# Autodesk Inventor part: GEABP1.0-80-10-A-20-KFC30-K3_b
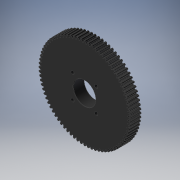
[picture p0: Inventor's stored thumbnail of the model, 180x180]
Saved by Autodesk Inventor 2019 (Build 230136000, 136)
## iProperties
Created: 2022-11
Part Number: GEABP1.0-80-10-A-20-KFC30-K3_b
Material: Generic
Catalog Web Link: www.cadenas.de
Description: GEABM, GEABMS, GEABMT, GEABP, GEABPS, GEABPT, GEABA, GEABAS, GEABAT_body-Plastic Spur Gears - Pressure Angle 20 Degrees, Module 0.5/0.8/1.0/1.5/2.0/2.5/3.0
Vendor: MISUMI
Document SubType Name: Modeling
Designer: psAdmin
Manufacturer: MISUMI
Mass: 46.6006 g
Surface Area: 152.098 cm^2
Volume: 46.6006 cm^3
Density: 1 g/cm^3
Appearance: PSOLRGB-175-175-175
Category: PARTsolutions
Company: MISUMI
Title: GEABP1.0-80-10-A-20-KFC30-K3
Author: Cadenas PARTsolutions
Comments: Plastic Spur Gears - Pressure Angle 20 Degrees, Module 0.5/0.8/1.0/1.5/2.0/2.5/3.0
PSOL_IDENT_0: {$CADENAS_DATA/23d-libs/misumi/metric/54_spur_gears/geabms20/geabms20.prj},408 {VTYP=3D},{NB=GEABP1.
PSOL_IDENT_1: 0-80-10-A-20-KFC30-K3_b},{LINA=GEABP1.0-80-10-A-20-KFC30-K3},{NN=GEABM, GEABMS, GEABMT, GEABP, GEABP
PSOL_IDENT_2: S, GEABPT, GEABA, GEABAS, GEABAT_body},{DATE=17.10.2022 23:48:33},{GEOMDATE=14.09.2022 05:11:00},{VE
PSOL_IDENT_3: RSION=},{LINEID=30},{WBVAR=MATSG,MATCR,NT,B,TS,PS,ALT1,ALT2,TPC,ALT11,ALT10,BS,ALT3,Z,J,ALT4,Q,R,S,T
PSOL_IDENT_4: ,ALT5,LFC,LTC,MALT5,ALT6,KFC,KTC,K},{WBNUMERIC=NT,B,BS,Z,J,Q,R,S,T,LFC,LTC,KFC,KTC,K}  {NB=GEABP1.0-
PSOL_IDENT_5: 80-10-A-20-KFC30-K3_b},{LINA=GEABP1.0-80-10-A-20-KFC30-K3},{KT=DUMMY},{PN=GEABP1.0-80-10-A-20-KFC30-
PSOL_IDENT_6: K3},{TYPE=GEABP},{MATSG=PW},{MATSGALG='MCN','MC Nylon','PW','Polyacetal White','PB','Polyacetal Blue'
PSOL_IDENT_7: },{MATCR=},{MATCRALG='','-','S45C','1045 Carbon Steel','SUS304','304 Stainless Steel'},{MOD=1.0},{MO
PSOL_IDENT_8: D1=1.0},{NT=80},{NTALG=15,16,18,20,22,24,25,26,28,30,32,35,36,40,45,48,50,55,60,70,75,80,90,100,120}
PSOL_IDENT_9: ,{B=10},{BALG=10,15},{TS=A},{TSALG='A','A','B','B'},{TSPN=-A},{PS=20},{PSALG='10','10','11','11','12'
PSOL_IDENT_10: ,'12','13','13','14','14','15','15','16','16','17','17','18','18','19','19','20','20','21','21','22'
PSOL_IDENT_11: ,'22','23','23','24','24','25','25','26','26','27','27','28','28'},{PSCRL='10','10','11','11','12','
PSOL_IDENT_12: 12','13','13','14','14','15','15','16','16','17','17','18','18','19','19','20','20','21','21','22','
PSOL_IDENT_13: 22','23','23','24','24','25','25','26','26','27','27','28','28'},{PSCRW='10','10','12','12','15','15'
PSOL_IDENT_14: ,'20','20'},{DD=80.0},{DD05=40},{DD08=64},{DD10=80},{DD15=120},{DD20=0},{DD25=0},{DD30=0},{D=82.0},{
PSOL_IDENT_15: D05=41},{D08=65.6},{D10=82},{D15=123},{D20=0},{D25=0},{D30=0},{G=77.50},{G05=38.75},{G08=62},{G10=77
PSOL_IDENT_16: .5},{G15=116.25},{G20=0},{G25=0},{G30=0},{H=0.0},{L=0},{LL1=0},{LL2=0.0},{M=-},{M3D=0},{P=20.00},{DD
PSOL_IDENT_17: 1=0},{CIFR=15},{CIFM=0},{CIFK=0},{CIFTAP=0},{ALT1=},{ALT1ALG='','Not applicable'},{ALT1PN=},{ALT2=},
PSOL_IDENT_18: {ALT2ALG='','Not applicable'},{TPC=N/A},{TPCALG='N/A'},{ALT2PN=},{KC=0},{ALT11=},{ALT11ALG='','Not a
PSOL_IDENT_19: pplicable'},{ALT11PN=},{DEG=0},{ALT10=},{ALT10ALG= '','Not applicable' },{ALT10PN=},{BS=0.0},{BSALG=
PSOL_IDENT_20: 0},{BSMIN=3},{BSMINALG=3.000},{BSMAX=0},{LL13D=0},{LL23D=0},{LBS=10},{ALT3=},{ALT3ALG= '','w/o Stepp
PSOL_IDENT_21: ed Hole','DHL','with DHL (Stepped Hole)','DHR','with DHR (Stepped Hole)' },{ALT3PN=},{ZJPN=},{ALT31=
PSOL_IDENT_22: 1},{ALT32=1},{Z=0},{ZALG=0},{ZMINL=22},{ZMAXL=73},{ZMINR=22},{ZMAXR=73},{ZPN=},{J=0.0},{JALG=0},{JMI
PSOL_IDENT_23: N=2},{JMAX=0},{JPN=},{ALT4=},{ALT4ALG= '','w/o WDH (Both Ends Stepped Hole)','WDH','with WDH (Both E
PSOL_IDENT_24: nds Stepped Hole)' },{ALT4PN=},{QRSTPN=},{LB=10.000},{Q=0},{QALG=0},{QMIN=22},{QMAX=73},{QPN=},{R=0}
PSOL_IDENT_25: ,{RALG=0},{RMIN=22},{RMAX=73},{RPN=},{S=0},{SALG=0},{SMIN=3},{SMAX=4},{SPN=},{T=0},{TALG=0},{TMIN=3}
PSOL_IDENT_26: ,{TMAX=0},{TPN=},{ALT5=},{ALT5ALG= '','w/o Side Slotted Hole','LFC','with LFC (Side Slotted Hole)','
PSOL_IDENT_27: LTC','with LTC (Side Slotted Hole)' },{LFC=0},{LFCALG=0},{LTC=0},{LTCALG=0},{LPCDMIN=28},{LPCDMAX=70
PSOL_IDENT_28: },{LCMAX=73},{MALT5=N/A},{MALT5ALG= 'N/A' },{LCMAX2=70},{C=0.0},{ALT5PN=},{ALT6=KFC},{ALT6ALG= '','w
PSOL_IDENT_29: /o Side Through Hole','KFC','with KFC (Side Through Hole)','KTC','with KTC (Side Through Hole)' },{A
PSOL_IDENT_30: LT6PN=-KFC},{KFTCPN=30-K3},{KFC=30},{KFCALG=[27:70/1]},{KFCPN=30},{KTC=0},{KTCALG=[0]},{KTCPN=},{KPC
PSOL_IDENT_31: DMIN1=27},{KPCDMAX1=-7},{KPCDMIN2=7},{KPCDMAX2=70},{K=3.0},{KALG=[3:6/0.5]},{KPCD=30},{KPN=-K3},{SCR
PSOL_IDENT_32: EW=0},{SCREWL=0},{AG=0},{PCD=30},{SHN=4},{SHDEG1=45},{SHDEG2=90},{PZQRDD2=20},{D1=1.125},{D2=2.25},{
PSOL_IDENT_33: D3=20},{D4=0.1},{D5=13.333333},{D6=12.307692},{D7=0.85},{D8=0.5},{D9=0.829978},{S1=15},{S2=0.5},{KR=
PSOL_IDENT_34: 15}
NB: GEABP1.0-80-10-A-20-KFC30-K3_b
NN: GEABM, GEABMS, GEABMT, GEABP, GEABPS, GEABPT, GEABA, GEABAS, GEABAT_body
NT: 80
NBSYN: $PN._b
LINA: GEABP1.0-80-10-A-20-KFC30-K3
CATALOG: Misumi
PN: GEABP1.0-80-10-A-20-KFC30-K3
MATSG: Polyacetal White
MATCR: -
MOD: 1.0
B: 10
TS: A
PS: 20
DD: 80
D: 82
G: 77.5
H: 0
L: 0
LL1: 0
LL2: 0
M: -
DD1: 0
ALT1: Not applicable
ALT2: Not applicable
TPC: N/A
ALT11: Not applicable
ALT10: Not applicable
BS: 0
ALT3: w/o Stepped Hole
Z: 0
J: 0
ALT4: w/o WDH (Both Ends Stepped Hole)
Q: 0
R: 0
S: 0
T: 0
ALT5: w/o Side Slotted Hole
LFC: 0
LTC: 0
MALT5: N/A
C: 0
ALT6: with KFC (Side Through Hole)
KFC: 30
KTC: 0
K: 3
SUPPLIER: MISUMI
ARTICLENO: GEABP1.0-80-10-A-20-KFC30-K3_b
BOMINFO: GEABP1.0-80-10-A-20-KFC30-K3
CREATOR: CADENAS GmbH
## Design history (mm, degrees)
sketch "_____3"
  geometry: L1 (10, 0)-(0, 0); L2 (0, 0)-(0, 40.5); L3 (0, 40.5)-(0.67, 43); L4 (0.67, 43)-(9.33, 43); L5 (9.33, 43)-(10, 40.5); L6 (10, 40.5)-(10, 0); L7 (10, 0)-(0, 0)
  constraints: 14 end point
revolve "Revolution1" sketch "_____3" stored, may be unused: angle "d0" = 360 deg
sketch "_____12"
  geometry: C1 r 164 at (0, 0); A1 r 41 centre (0, 0) between (-40.999, 0.33) and (-40.999, -0.33); A2 r 0.1 centre (-40.899, -0.329) between (-40.999, -0.33) and (-40.938, -0.421); A3 r 13.333 centre (-35.679, 11.831) between (-40.938, -0.421) and (-39.992, -0.785); A4 r 0.83 centre (-39.724, 0) between (-39.992, -0.785) and (-39.882, -0.815); A5 r 12.308 centre (-42.24, -12.894) between (-39.094, -0.996) and (-39.882, -0.815); A6 r 0.5 centre (-39.222, -1.479) between (-38.722, -1.46) and (-39.094, -0.996); A7 r 38.75 centre (0, 0) between (-38.722, -1.46) and (-38.718, -1.583); A8 r 0.5 centre (-39.217, -1.603) between (-39.052, -2.075) and (-38.718, -1.583); A9 r 12.308 centre (-43.122, 9.541) between (-39.823, -2.317) and (-39.052, -2.075); A10 r 0.83 centre (-39.601, -3.117) between (-39.823, -2.317) and (-39.931, -2.355); A11 r 13.333 centre (-34.641, -14.594) between (-39.931, -2.355) and (-40.845, -2.792); A12 r 0.1 centre (-40.798, -2.881) between (-40.845, -2.792) and (-40.898, -2.888); A13 r 41 centre (0, 0) between (-40.898, -2.888) and (-40.846, -3.546); A14 r 0.1 centre (-40.747, -3.537) between (-40.846, -3.546) and (-40.779, -3.632); A15 r 13.333 centre (-36.497, 8.995) between (-40.779, -3.632) and (-39.807, -3.921); A16 r 0.83 centre (-39.601, -3.117) between (-39.807, -3.921) and (-39.695, -3.941); A17 r 12.308 centre (-41.098, -16.169) between (-38.896, -4.06) and (-39.695, -3.941); A18 r 0.5 centre (-38.985, -4.552) between (-38.489, -4.494) and (-38.896, -4.06); A19 r 38.75 centre (0, 0) between (-38.489, -4.494) and (-38.474, -4.615); A20 r 0.5 centre (-38.971, -4.675) between (-38.769, -5.132) and (-38.474, -4.615); A21 r 12.308 centre (-43.737, 6.128) between (-39.518, -5.434) and (-38.769, -5.132); A22 r 0.83 centre (-39.235, -6.214) between (-39.518, -5.434) and (-39.623, -5.48); A23 r 13.333 centre (-33.389, -17.267) between (-39.623, -5.48) and (-40.5, -5.988); A24 r 0.1 centre (-40.447, -6.073) between (-40.5, -5.988) and (-40.546, -6.087); A25 r 41 centre (0, 0) between (-40.546, -6.087) and (-40.442, -6.74); A26 r 0.1 centre (-40.344, -6.723) between (-40.442, -6.74) and (-40.368, -6.82); A27 r 13.333 centre (-37.09, 6.104) between (-40.368, -6.82) and (-39.377, -7.032); A28 r 0.83 centre (-39.235, -6.214) between (-39.377, -7.032) and (-39.263, -7.044); A29 r 12.308 centre (-39.703, -19.343) between (-38.457, -7.099) and (-39.263, -7.044); A30 r 0.5 centre (-38.508, -7.596) between (-38.017, -7.5) and (-38.457, -7.099); A31 r 38.75 centre (0, 0) between (-38.017, -7.5) and (-37.993, -7.62); A32 r 0.5 centre (-38.484, -7.718) between (-38.247, -8.158) and (-37.993, -7.62); A33 r 12.308 centre (-44.083, 2.677) between (-38.97, -8.518) and (-38.247, -8.158); A34 r 0.83 centre (-38.626, -9.273) between (-38.97, -8.518) and (-39.071, -8.572); A35 r 13.333 centre (-31.931, -19.833) between (-39.071, -8.572) and (-39.905, -9.147); A36 r 0.1 centre (-39.846, -9.227) between (-39.905, -9.147) and (-39.943, -9.25); A37 r 41 centre (0, 0) between (-39.943, -9.25) and (-39.789, -9.892); A38 r 0.1 centre (-39.692, -9.868) between (-39.789, -9.892) and (-39.709, -9.966); A39 r 13.333 centre (-37.455, 3.175) between (-39.709, -9.966) and (-38.704, -10.1); A40 r 0.83 centre (-38.626, -9.273) between (-38.704, -10.1) and (-38.59, -10.103); A41 r 12.308 centre (-38.063, -22.399) between (-37.782, -10.094) and (-38.59, -10.103); A42 r 0.5 centre (-37.793, -10.594) between (-37.312, -10.459) and (-37.782, -10.094); A43 r 38.75 centre (0, 0) between (-37.312, -10.459) and (-37.278, -10.577); A44 r 0.5 centre (-37.759, -10.714) between (-37.489, -11.134) and (-37.278, -10.577); A45 r 12.308 centre (-44.157, -0.79) between (-38.182, -11.549) and (-37.489, -11.134); A46 r 0.83 centre (-37.78, -12.275) between (-38.182, -11.549) and (-38.278, -11.611); A47 r 13.333 centre (-30.277, -22.277) between (-38.278, -11.611) and (-39.065, -12.25); A48 r 0.1 centre (-38.999, -12.325) between (-39.065, -12.25) and (-39.094, -12.355); A49 r 41 centre (0, 0) between (-39.094, -12.355) and (-38.89, -12.983); A50 r 0.1 centre (-38.795, -12.952) between (-38.89, -12.983) and (-38.804, -13.051); A51 r 13.333 centre (-37.589, 0.227) between (-38.804, -13.051) and (-37.792, -13.105); A52 r 0.83 centre (-37.78, -12.275) between (-37.792, -13.105) and (-37.678, -13.099); A53 r 12.308 centre (-36.188, -25.316) between (-36.873, -13.028) and (-37.678, -13.099); A54 r 0.5 centre (-36.845, -13.527) between (-36.376, -13.355) and (-36.873, -13.028); A55 r 38.75 centre (0, 0) between (-36.376, -13.355) and (-36.334, -13.469); A56 r 0.5 centre (-36.802, -13.643) between (-36.499, -14.041) and (-36.334, -13.469); A57 r 12.308 centre (-43.959, -4.252) between (-37.158, -14.509) and (-36.499, -14.041); A58 r 0.83 centre (-36.7, -15.202) between (-37.158, -14.509) and (-37.249, -14.579); A59 r 13.333 centre (-28.435, -24.584) between (-37.249, -14.579) and (-37.983, -15.277); A60 r 0.1 centre (-37.911, -15.347) between (-37.983, -15.277) and (-38.004, -15.384); A61 r 41 centre (0, 0) between (-38.004, -15.384) and (-37.751, -15.995); A62 r 0.1 centre (-37.659, -15.956) between (-37.751, -15.995) and (-37.661, -16.056); A63 r 13.333 centre (-37.491, -2.723) between (-37.661, -16.056) and (-36.648, -16.03); A64 r 0.83 centre (-36.7, -15.202) between (-36.648, -16.03) and (-36.534, -16.015)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; 1 further point
  constraints: 1920 point on circle, 961 centre point
extrude "Extrusion1" cut sketch "_____12" distance "d1" = 10; taper "d2" = 0 deg
sketch "Sketch3"
  geometry: 1 further point
hole "Hole1" sketch "Sketch3" at (0, 0) diameter "d3" = 20; stored, may be unused: countersink angle "d7" = 90 deg, drill point angle "d9" = 0 deg; dims "d4" = 6, "d5" = 4, "d6" = 2, "d8" = 10
sketch "_____5"
  geometry: L1 (500, 0)-(-500, 0); L2 (9.7, 10)-(10, 10); L3 (10, 10)-(10, 10.3); L4 (10, 10.3)-(9.7, 10)
  constraints: 8 end point
revolve "Revolution2" sketch "_____5" stored, may be unused: angle "d10" = 360 deg
sketch "_____13"
  geometry: L1 (500, 0)-(-500, 0); L2 (0, 10.3)-(0, 10); L3 (0, 10)-(0.3, 10); L4 (0.3, 10)-(0, 10.3)
  constraints: 8 end point
revolve "Revolution3" sketch "_____13" stored, may be unused: angle "d11" = 360 deg
sketch "Sketch6"
  geometry: 1 further point
hole "Hole2" sketch "Sketch6" at (-9.742, 11.406) diameter "d12" = 3; stored, may be unused: countersink angle "d16" = 90 deg, drill point angle "d18" = 0 deg; dims "d13" = 6, "d14" = 4, "d15" = 2, "d17" = 10
pattern_linear "Rectangular Pattern1" dims "d21" = 21.2132, "d24" = 21.2132
body "Solid1"
